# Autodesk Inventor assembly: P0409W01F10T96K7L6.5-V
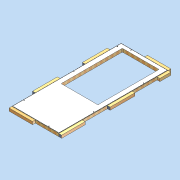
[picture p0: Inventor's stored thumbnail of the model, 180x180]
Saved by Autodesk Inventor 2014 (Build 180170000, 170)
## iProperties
Created: 2011-04
Part Number: P0409W01F10T96K7L6.5-V
Document SubType Name: Assembly
Designer: david.appleford
Description: 1w x 2.25w 01 Panel - 7 Locks 6.5 Lugs
Mass: 35000 g
Surface Area: 55673.3 cm^2
Volume: 155474 cm^3
Density: 0.225119 g/cm^3
Cost Center: £185.00
Justset: False
Title: 1w x 2.25w 01 Panel - 7 Locks 6.5 Lugs
Author: david.appleford
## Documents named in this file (5)
- C:\Documents and Settings\john.everitt\Local Settings\My Documents\Vault\Production MkII\Virtual Elements\Virtual Walls\Virtual Timber + MgO\P0409W01F10T96K7L6.5-V.iam
- C:\Documents and Settings\john.everitt\Local Settings\My Documents\Vault\Production MkII\VIRTUAL ELEMENTS\Virtual Lugs\Superceded Lugs\LA02C3V.ipt
- C:\Documents and Settings\john.everitt\Local Settings\My Documents\Vault\Production MkII\VIRTUAL ELEMENTS\Virtual Lugs\Superceded Lugs\LA02M3V.ipt
- C:\Documents and Settings\john.everitt\Local Settings\My Documents\Vault\Production MkII\VIRTUAL ELEMENTS\Virtual Lugs\Superceded Lugs\LA01C3V.ipt
- C:\Documents and Settings\john.everitt\Local Settings\My Documents\Vault\Production MkII\Virtual Elements\Virtual Walls\Virtual Timber + MgO\P0409W01F10T96K7-V.ipt
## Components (8 placed, 4 different names)
1. P0409W01F10T96K7-V:1 — Mate:1, Flush:1, Flush:2, Mate:2, Flush:3, Flush:4, Mate:4, Flush:7, Flush:8, Mate:5, Mate:6, Flush:9, Flush:10, Mate:7, Flush:11, Mate:14, Flush:12, Flush:13
2. LA02C3V:1 — Mate:1, Flush:1, Flush:2, Mate:9, Mate:13
3. LA02C3V:2 — Mate:2, Flush:3, Flush:4
4. LA02C3V:3 — Mate:4, Flush:7, Flush:8
5. LA02M3V:5 — Mate:6, Flush:9, Mate:12
6. LA02M3V:2 — Mate:5, Flush:10, Mate:12, Mate:13
7. LA02M3V:4 — Mate:7, Flush:11, Mate:9
8. LA01C3V:1 — Mate:14, Flush:12, Flush:13
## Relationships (21: Flush 11, Mate 10)
- Mate:1: P0409W01F10T96K7-V:1 ↔ LA02C3V:1
- Flush:1: P0409W01F10T96K7-V:1 ↔ LA02C3V:1
- Flush:2: P0409W01F10T96K7-V:1 ↔ LA02C3V:1
- Mate:2: P0409W01F10T96K7-V:1 ↔ LA02C3V:2
- Flush:3: P0409W01F10T96K7-V:1 ↔ LA02C3V:2
- Flush:4: P0409W01F10T96K7-V:1 ↔ LA02C3V:2
- Mate:4: P0409W01F10T96K7-V:1 ↔ LA02C3V:3
- Flush:7: P0409W01F10T96K7-V:1 ↔ LA02C3V:3
- Flush:8: P0409W01F10T96K7-V:1 ↔ LA02C3V:3
- Mate:5: P0409W01F10T96K7-V:1 ↔ LA02M3V:2
- Mate:6: P0409W01F10T96K7-V:1 ↔ LA02M3V:5
- Flush:9: P0409W01F10T96K7-V:1 ↔ LA02M3V:5
- Flush:10: P0409W01F10T96K7-V:1 ↔ LA02M3V:2
- Mate:7: P0409W01F10T96K7-V:1 ↔ LA02M3V:4
- Flush:11: P0409W01F10T96K7-V:1 ↔ LA02M3V:4
- Mate:9: LA02C3V:1 ↔ LA02M3V:4
- Mate:12: LA02M3V:5 ↔ LA02M3V:2
- Mate:13: LA02C3V:1 ↔ LA02M3V:2
- Mate:14: P0409W01F10T96K7-V:1 ↔ LA01C3V:1
- Flush:12: P0409W01F10T96K7-V:1 ↔ LA01C3V:1
- Flush:13: P0409W01F10T96K7-V:1 ↔ LA01C3V:1
## Named parameters: t = 1 mm, Cl = 2 mm
